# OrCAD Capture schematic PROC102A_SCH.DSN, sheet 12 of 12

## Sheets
12 09.IO LINK TRANCIEVER[4:8]: size C; title: IO LINK TRANCIEVER[5:8]
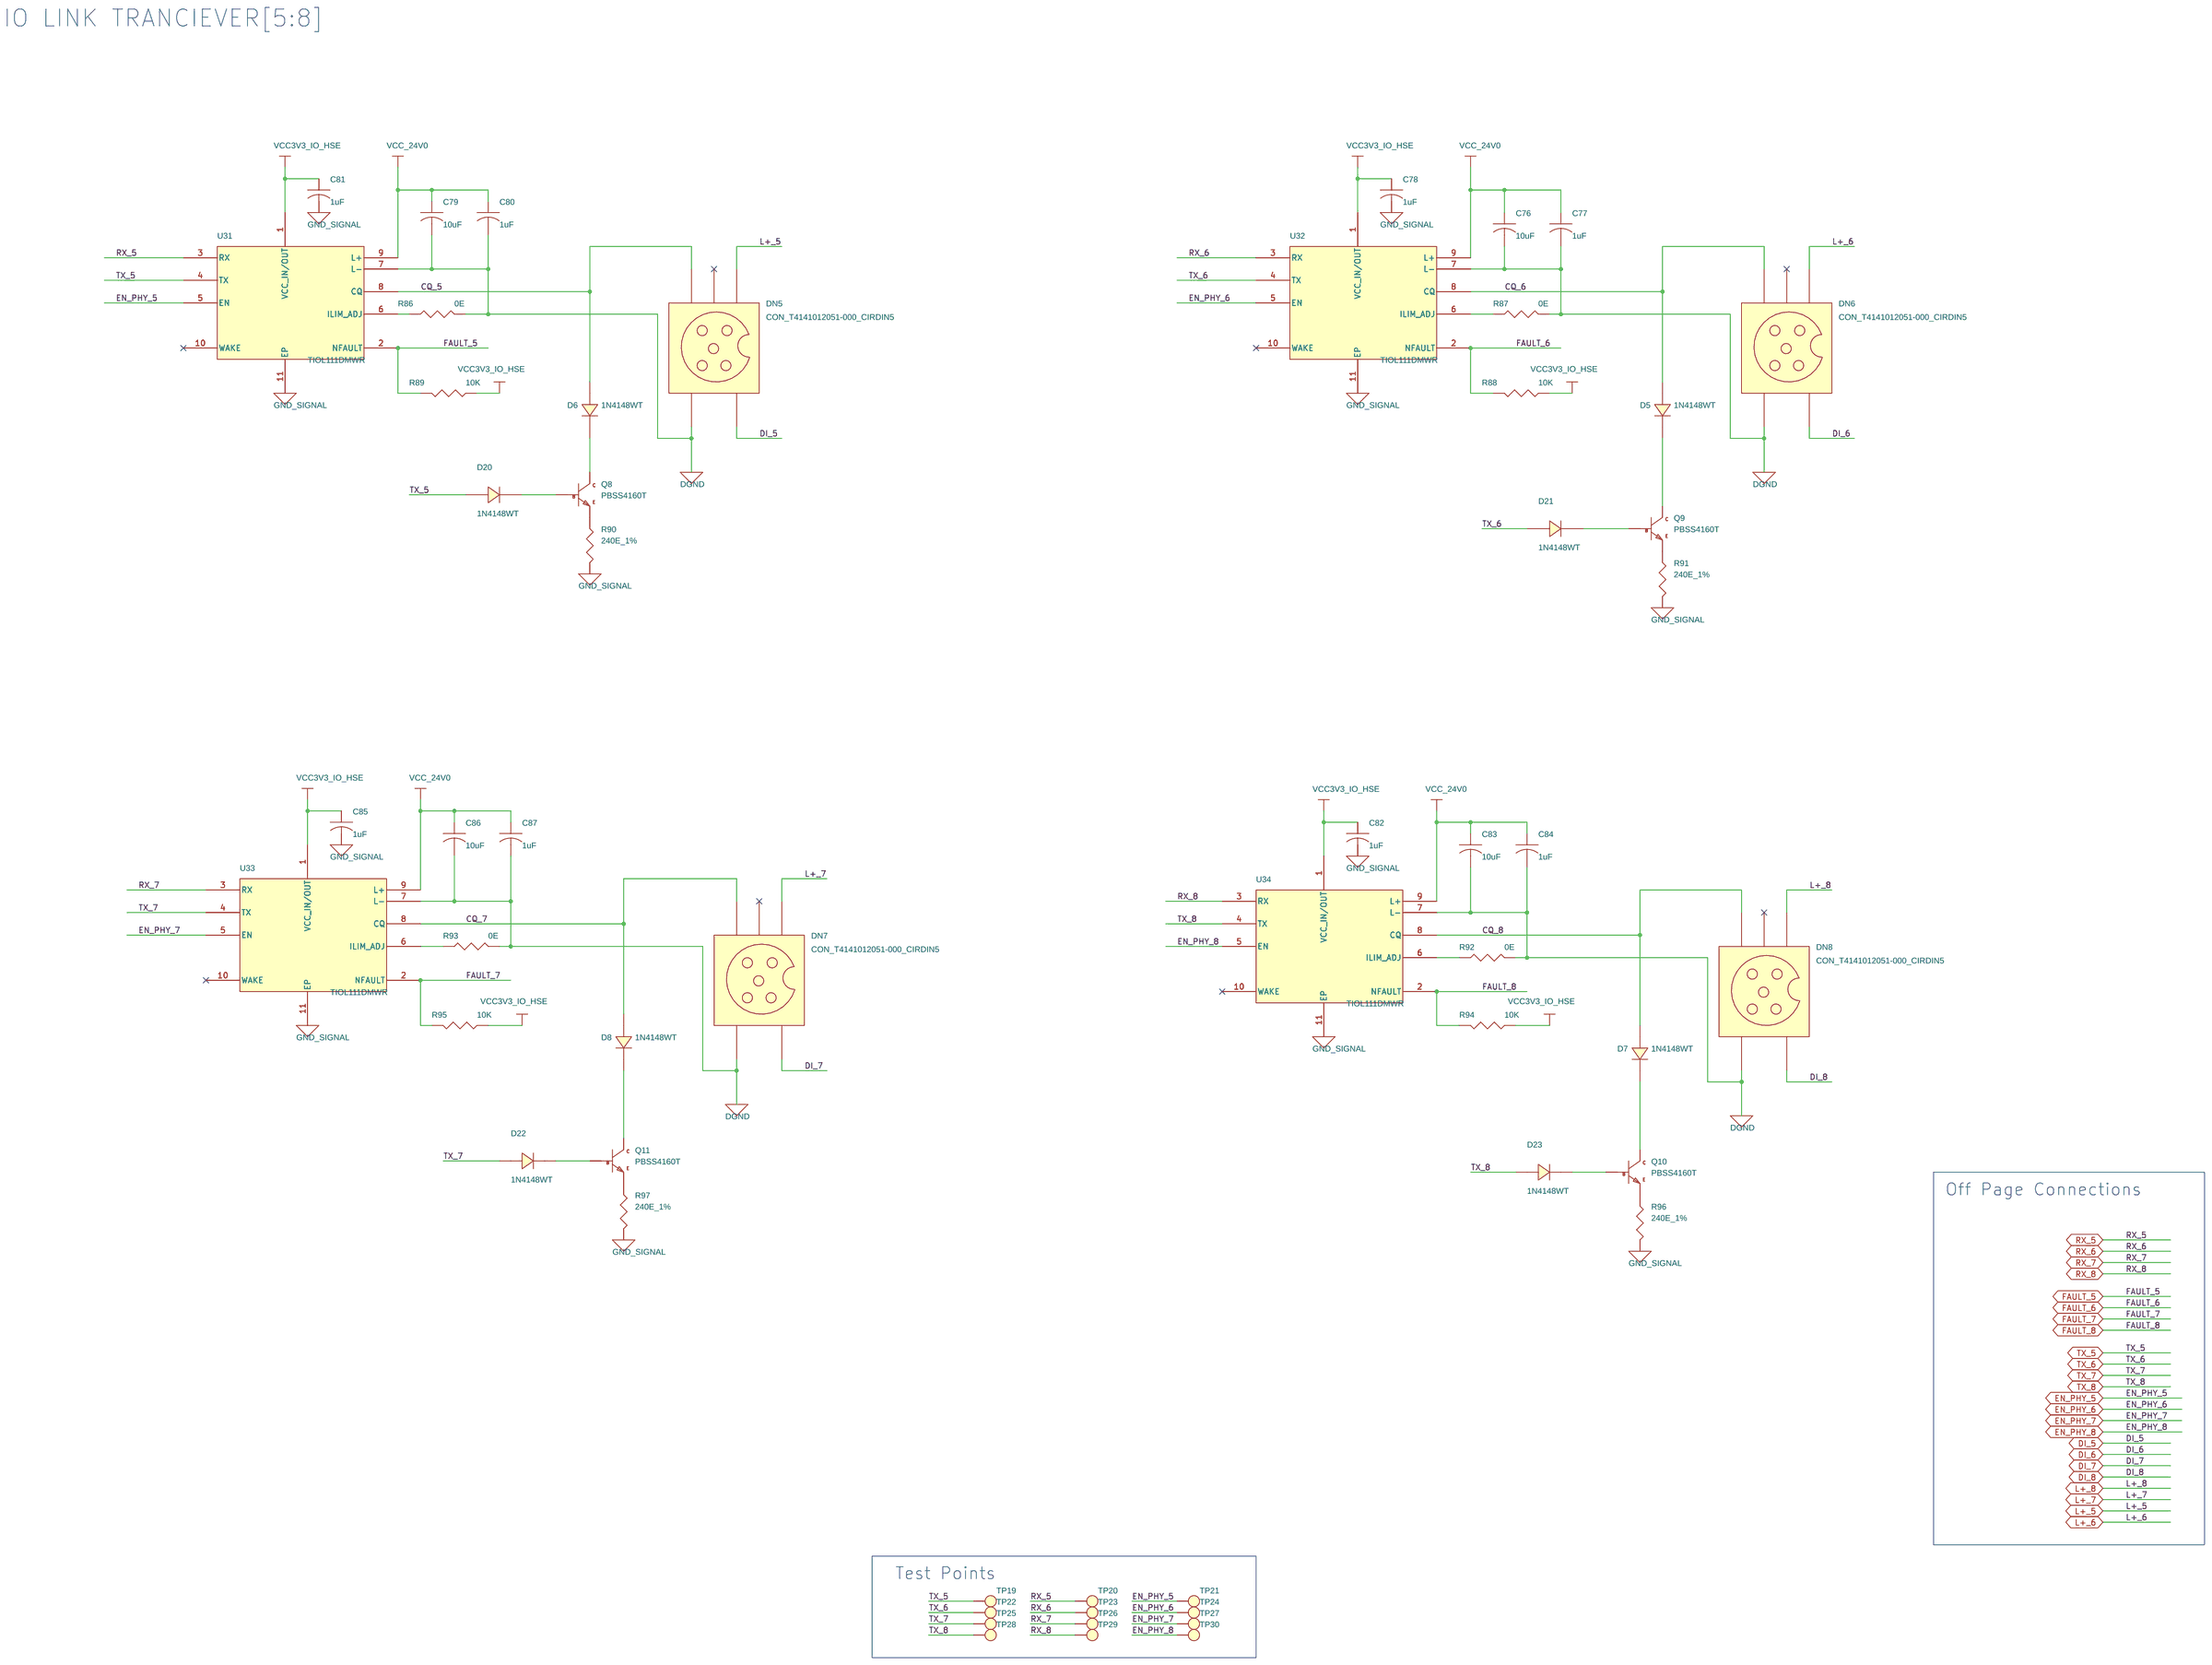
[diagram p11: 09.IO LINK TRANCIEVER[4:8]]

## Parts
C76  10uF  [CAP1206_2]
C77  1uF  [CAP0805_1-5]
C78  1uF  [CAP0402_0-75]
C79  10uF  [CAP1206_2]
C80  1uF  [CAP0805_1-5]
C81  1uF  [CAP0402_0-75]
C82  1uF  [CAP0402_0-75]
C83  10uF  [CAP1206_2]
C84  1uF  [CAP0805_1-5]
C85  1uF  [CAP0402_0-75]
C86  10uF  [CAP1206_2]
C87  1uF  [CAP0805_1-5]
D5  1N4148WT  [DIO_SOD523]
D6  1N4148WT  [DIO_SOD523]
D7  1N4148WT  [DIO_SOD523]
D8  1N4148WT  [DIO_SOD523]
D20  1N4148WT  [DIO_SOD523]
D21  1N4148WT  [DIO_SOD523]
D22  1N4148WT  [DIO_SOD523]
D23  1N4148WT  [DIO_SOD523]
DN5  CON_T4141012051-000_CIRDIN5  [CON_CIRDIN5_T4141012051_S_S_T_23]
DN6  CON_T4141012051-000_CIRDIN5  [CON_CIRDIN5_T4141012051_S_S_T_23]
DN7  CON_T4141012051-000_CIRDIN5  [CON_CIRDIN5_T4141012051_S_S_T_23]
DN8  CON_T4141012051-000_CIRDIN5  [CON_CIRDIN5_T4141012051_S_S_T_23]
Q8  PBSS4160T  [SOT23-123_1-1]
Q9  PBSS4160T  [SOT23-123_1-1]
Q10  PBSS4160T  [SOT23-123_1-1]
Q11  PBSS4160T  [SOT23-123_1-1]
R86  0E  [RES0402_0-5]
R87  0E  [RES0402_0-5]
R88  10K  [RES0402_0-5]
R89  10K  [RES0402_0-5]
R90  240E_1%  [RES0402_0-5]
R91  240E_1%  [RES0402_0-5]
R92  0E  [RES0402_0-5]
R93  0E  [RES0402_0-5]
R94  10K  [RES0402_0-5]
R95  10K  [RES0402_0-5]
R96  240E_1%  [RES0402_0-5]
R97  240E_1%  [RES0402_0-5]
TP19  TP20_SMD  [TP20_SMD]
TP20  TP20_SMD  [TP20_SMD]
TP21  TP20_SMD  [TP20_SMD]
TP22  TP20_SMD  [TP20_SMD]
TP23  TP20_SMD  [TP20_SMD]
TP24  TP20_SMD  [TP20_SMD]
TP25  TP20_SMD  [TP20_SMD]
TP26  TP20_SMD  [TP20_SMD]
TP27  TP20_SMD  [TP20_SMD]
TP28  TP20_SMD  [TP20_SMD]
TP29  TP20_SMD  [TP20_SMD]
TP30  TP20_SMD  [TP20_SMD]
U31  TIOL111DMWR  [VSON10_19-68_120X100_1]
U32  TIOL111DMWR  [VSON10_19-68_120X100_1]
U33  TIOL111DMWR  [VSON10_19-68_120X100_1]
U34  TIOL111DMWR  [VSON10_19-68_120X100_1]

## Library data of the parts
C76 C79 C83 C86 = CAP: CAP CERAMIC 10uF 50V 10% X5R AUTO 1206; Chkd/date: MANIRAJA/261018; Crtd /date: ALVY/261018; Custom_Duty: 15%; Customs_HS_Code: 85322990; Distributor_name: DIGIKEY; Distributor_part_number: 490-12456-1-ND; Footprint Path: Y:\MIS_DATABASE\Library\ALTIUM_TOOL\PCB_FOOTPRINTS\Altium_Footprint_Lib.PcbLib; Height: 1.80MM; Library Path: Y:\MIS_DATABASE\Library\ALTIUM_TOOL\SCHEMATICS_PARTS\MS_DISCRETE_Library.schlib; Mfr_name: MURATA; Mfr_part_number: GRT31CR61H106KE01L; Mistral Part No: 120011060019-R; Package: 1206; Part_type: CAPACITORS\CERAMIC; Project: LRDE_ABCMV2_MB; RoHS: RoHS; Temperature: -55°C+85°C; Tolerance: 10%; Voltage: 50V; Wattage: NA; Weight: 16.2mg; Datasheet: Y:\MIS_DATABASE\DATASHEETS\CAPACITORS\GRT31CR61H106KE01L.PDF
C77 C80 C84 C87 = CAP: CAP CERAMIC 1uF 50V 10% X7R 0805; Chkd/date: MANIRAJA/100920; Crtd /date: ALVY/100920; Custom_Duty: 15%; Customs_HS_Code: 85322990; Distributor_name: DIGIKEY; Distributor_part_number: 732-7678-1-ND; Footprint Path: Y:\MIS_DATABASE\Library\ALTIUM_TOOL\PCB_FOOTPRINTS\Altium_Footprint_Lib.PcbLib; Height: 1.35MM; Library Path: Y:\MIS_DATABASE\Library\ALTIUM_TOOL\SCHEMATICS_PARTS\MS_DISCRETE_Library.schlib; Mfr_name: WURTH ELECTRONICS; Mfr_part_number: 885012207103; Mistral Part No: 120011010018-R; Package: 0805; Part_type: CAPACITORS\CERAMIC; Project: AM64x-IO LINK BRD; RoHS: RoHS; Temperature: -55°C+125°C; Tolerance: 10%; Voltage: 50V; Wattage: NA; Weight: 36mg; Datasheet: Y:\MIS_DATABASE\DATASHEETS\CAPACITORS\885012207103.PDF
C78 C81 C82 C85 = CAP: CAP CERAMIC 1uF 10V 20% X5R 0402; Chkd/date: MANIRAJA/210820; Crtd /date: ALVY/190820; Custom_Duty: 15%; Customs_HS_Code: 85322990; Distributor_name: DIGIKEY; Distributor_part_number: 732-7489-1-ND; Footprint Path: Y:\MIS_DATABASE\Library\ALTIUM_TOOL\PCB_FOOTPRINTS\Altium_Footprint_Lib.PcbLib; Height: 0.55MM; Library Path: Y:\MIS_DATABASE\Library\ALTIUM_TOOL\SCHEMATICS_PARTS\MS_DISCRETE_Library.schlib; Mfr_name: WURTH ELECTRONICS; Mfr_part_number: 885012105012; Mistral Part No: 120020080009-R; Package: 0402; Part_type: CAPACITORS\CERAMIC; Project: AM64x_EVM_BRD; RoHS: RoHS; Temperature: -55°C+85°C; Tolerance: 20%; Voltage: 10V; Wattage: NA; Weight: 0.65mg; Datasheet: Y:\MIS_DATABASE\DATASHEETS\CAPACITORS\885012105012.PDF
D5-D8 D20-D23 = DIODE: DIODE SWITCH 75V 10mA SOD523; Chkd/date: SUHAS/041010; Crtd /date: MAZHAR/110210; Custom_Duty: 15%; Customs_HS_Code: 85412900; Distributor_name: DIGIKEY; Distributor_part_number: 1N4148WTCT-ND; Height: 0.70MM; Mfr_name: FAIRCHILD; Mistral Part No: 130010020017-R; Package: SOD523; Part_type: DIODE\SWITCHING; Project: NPOL_PREAMP; RoHS: RoHS; Temperature: -55°C+150°C; Tolerance: 20%; Voltage: 75V; Weight: NA; Datasheet: Y:\MIS_DATABASE\DATASHEETS\DISCRETES\DIODES\1N4148WT-F.PDF
DN5-DN8 = CON_T4143012051_CIRDIN5_S: CON CIRCULAR 5POS FEMALE ST TH; Chkd/date: MANIRAJA/280820; Crtd /date: ALVY/280820; Custom_Duty: 24%; Customs_HS_Code: 85369090; Distributor_name: DIGIKEY; Distributor_part_number: A126851-ND; Footprint Path: Y:\MIS_DATABASE\Library\ALTIUM_TOOL\PCB_FOOTPRINTS\Altium_Footprint_Lib.PcbLib; Height: 23.00MM; Library Path: Y:\MIS_DATABASE\Library\ALTIUM_TOOL\SCHEMATICS_PARTS\MS_CONNECTOR_Library.schlib; Mfr_name: TE CONNECTIVITY; Mfr_part_number: T4141012051-000; Mistral Part No: 150020080008-R; Package: THRU-HOLE; Part_type: CONNECTOR\CIRDIN; Project: AM64x_EVM_TESTJIG_BRD; RoHS: RoHS; Temperature: -40°C+85°C; Tolerance: NA; Voltage: NA; Wattage: NA; Weight: 16500mg; Datasheet: Y:\MIS_DATABASE\DATASHEETS\CONNECTORS\T41410120X1-000.PDF
Q8-Q11 = NPN_123_SOT23-3: TRANSISTOR NPN 60V 1A SOT23-3; Chkd/date: MANIRAJA/220720; Crtd /date: ALVY/210720; Custom_Duty: 15%; Customs_HS_Code: 85412900; Distributor_name: DIGIKEY; Distributor_part_number: 1727-3939-1-ND; Footprint Path: Y:\MIS_DATABASE\Library\ALTIUM_TOOL\PCB_FOOTPRINTS\Altium_Footprint_Lib.PcbLib; Height: 1.10MM; Library Path: Y:\MIS_DATABASE\Library\ALTIUM_TOOL\SCHEMATICS_PARTS\MS_TRANSISTOR_Library.schlib; Mfr_name: NXP SEMICONDUCTORS; Mfr_part_number: PBSS4160T,215; Mistral Part No: 130020070017-R; Package: SOT23-3; Part_type: TRANSISTOR\BIPOLAR; Project: AM64x-IO LINK BRD; RoHS: RoHS; Temperature: -65°C+150°C; Tolerance: NA; Voltage: NA; Wattage: NA; Weight: 8mg; Datasheet: Y:\MIS_DATABASE\DATASHEETS\DISCRETES\TRANSISTORS_FETS\PBSS4160T.PDF
R86 R87 R92 R93 = RESISTOR: RES 0E 1/16W JUMPER 0402; Chkd/date: VASANTHA/201216; Crtd /date: MUDDU/190810; Custom_Duty: 15%; Customs_HS_Code: 85332119; Distributor_name: DIGIKEY; Distributor_part_number: 541-0.0JCT-ND; Footprint Path: Y:\MIS_DATABASE\Library\ALTIUM_TOOL\PCB_FOOTPRINTS\Altium_Footprint_Lib.PcbLib; Height: 0.40MM; Library Path: Y:\MIS_DATABASE\Library\ALTIUM_TOOL\SCHEMATICS_PARTS\MS_DISCRETE_Library.schlib; Mfr_name: VISHAY; Mfr_part_number: CRCW04020000Z0ED; Mistral Part No: 110010080019-R; Package: 0402; Part_type: RESISTORS\FIXED; Project: PB_BUGBASE; RoHS: RoHS; Temperature: -55°C+155°C; Tolerance: NA; Voltage: NA; Wattage: 1/16W; Weight: 0.65mg; Datasheet: Y:\MIS_DATABASE\DATASHEETS\RESISTORS\CRCW0603.PDF
R88 R89 R94 R95 = RESISTOR: RES 10K 1/16W 5% 0402; Chkd/date: VASANTHA/061216; Crtd /date: MAZHAR/230805; Custom_Duty: 15%; Customs_HS_Code: 85332119; Distributor_name: DIGIKEY; Distributor_part_number: 311-10KJRCT-ND; Footprint Path: Y:\MIS_DATABASE\Library\ALTIUM_TOOL\PCB_FOOTPRINTS\Altium_Footprint_Lib.PcbLib; Height: 0.40MM; Library Path: Y:\MIS_DATABASE\Library\ALTIUM_TOOL\SCHEMATICS_PARTS\MS_DISCRETE_Library.schlib; Mfr_name: YAGEO AMERICA; Mfr_part_number: RC0402JR-0710KL; Mistral Part No: 110011060021-R; Package: 0402; Part_type: RESISTORS\FIXED; Project: HSE; RoHS: RoHS; Temperature: -55°C+155°C; Tolerance: 5%; Voltage: NA; Wattage: 1/16W; Weight: 0.65mg; Datasheet: Y:\MIS_DATABASE\DATASHEETS\RESISTORS\RCXXXXL-SER_MAR18.PDF
R90 R91 R96 R97 = RESISTOR: RES 240E 1/10W 1% 0402; Chkd/date: MAZHAR/150611; Crtd /date: BAVISH/020611; Custom_Duty: 15%; Customs_HS_Code: 85332119; Distributor_name: DIGIKEY; Distributor_part_number: P240LCT-ND; Footprint Path: Y:\MIS_DATABASE\Library\ALTIUM_TOOL\PCB_FOOTPRINTS\Altium_Footprint_Lib.PcbLib; Height: 0.40MM; Library Path: Y:\MIS_DATABASE\Library\ALTIUM_TOOL\SCHEMATICS_PARTS\MS_DISCRETE_Library.schlib; Mfr_name: PANASONIC-ECG; Mfr_part_number: ERJ-2RKF2400X; Mistral Part No: 110011060017-R; Package: 0402; Part_type: RESISTORS\FIXED; Project: AM4515_EVM_LCD; RoHS: RoHS; Temperature: -55°C+155°C; Tolerance: 1%; Voltage: NA; Wattage: 1/10W; Weight: 0.8mg; Datasheet: Y:\MIS_DATABASE\DATASHEETS\RESISTORS\PAN-ERJSER_NOV17.PDF
TP19-TP30 = TESTPOINT: TESTPOINT CIR 20 SMD; Chkd/date: SHREESHAIL/171006; Crtd /date: MAZHAR/171006; Custom_Duty: NA; Customs_HS_Code: NA; Distributor_name: NA; Distributor_part_number: NA; Footprint Path: Y:\MIS_DATABASE\Library\ALTIUM_TOOL\PCB_FOOTPRINTS\Altium_Footprint_Lib.PcbLib; Height: NA; Library Path: Y:\MIS_DATABASE\Library\ALTIUM_TOOL\SCHEMATICS_PARTS\MS_DISCRETE_Library.schlib; MECHANICAL 3D STEP FILE: NA; Mfr_name: LOCAL; Mistral Part No: NA; Package: SMD; Project: BT MODULE_CSRBC04; RoHS: NA; Temperature: NA; Tolerance: NA; Voltage: NA; Wattage: NA; Weight: NA; Datasheet: NA
U31-U34 = TIOL111_VSON10: IC IO-LINK DEVICE TRANSCEIVER WITH INTEGRATED SURGE PROTECTION VSON10; Chkd/date: MANIRAJA/210720; Crtd /date: ALVY/170720; Custom_Duty: 15%; Customs_HS_Code: 85423100; Distributor_name: DIGIKEY; Distributor_part_number: 296-49943-1-ND; Footprint Path: Y:\MIS_DATABASE\Library\ALTIUM_TOOL\PCB_FOOTPRINTS\Altium_Footprint_Lib.PcbLib; Height: 1.00MM; Library Path: Y:\MIS_DATABASE\Library\ALTIUM_TOOL\SCHEMATICS_PARTS\MS_MISCINTERFACE_Library.schlib; Mfr_name: TEXAS INSTRUMENTS; Mistral Part No: 141020070002-R; Package: VSON10; Part_type: ICS\INTERFACE\TRANSCEIVER; Project: AM64x-GP_EVM BRD; RoHS: RoHS; Temperature: -40°C+125°C; Tolerance: NA; Voltage: NA; Wattage: NA; Weight: 19mg; Datasheet: Y:\MIS_DATABASE\DATASHEETS\ICS\DIGITAL\BUSTRANSCEIVER\TIOL111.PDF

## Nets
DGND: C76.2 C77.2 C78.2 C79.2 C80.2 C81.2 C82.2 C83.2 C84.2 C85.2 C86.2 C87.2 DN5.3 DN6.3 DN7.3 DN8.3 R86.2 R87.2 R90.2 R91.2 R92.2 R93.2 R96.2 R97.2 U31.7(L-) U31.11(EP) U32.7(L-) U32.11(EP) U33.7(L-) U33.11(EP) U34.7(L-) U34.11(EP) ; also on sheet 5 6 7 8 9 10 11
VCC3V3_IO_HSE: C78.1 C81.1 C82.1 C85.1 R88.2 R89.2 R94.2 R95.2 U31.1(VCC_IN/OUT) U32.1(VCC_IN/OUT) U33.1(VCC_IN/OUT) U34.1(VCC_IN/OUT) ; also on sheet 5 6 7 8 9 10 11
VCC_24V0: C76.1 C77.1 C79.1 C80.1 C83.1 C84.1 C86.1 C87.1 U31.9(L+) U32.9(L+) U33.9(L+) U34.9(L+) ; also on sheet 8 9 10 11
CQ_5: D6.2(A) DN5.4 U31.8(CQ)
CQ_6: D5.2(A) DN6.4 U32.8(CQ)
CQ_7: D8.2(A) DN7.4 U33.8(CQ)
CQ_8: D7.2(A) DN8.4 U34.8(CQ)
DI_5: DN5.2 ; also on sheet 9
DI_6: DN6.2 ; also on sheet 9
DI_7: DN7.2 ; also on sheet 9
DI_8: DN8.2 ; also on sheet 9
EN_PHY_5: TP21.1(TP) U31.5(EN) ; also on sheet 6
EN_PHY_6: TP24.1(TP) U32.5(EN) ; also on sheet 6
EN_PHY_7: TP27.1(TP) U33.5(EN) ; also on sheet 6
EN_PHY_8: TP30.1(TP) U34.5(EN) ; also on sheet 6
FAULT_5: R89.1 U31.2(NFAULT) ; also on sheet 7
FAULT_6: R88.1 U32.2(NFAULT) ; also on sheet 7
FAULT_7: R95.1 U33.2(NFAULT) ; also on sheet 7
FAULT_8: R94.1 U34.2(NFAULT) ; also on sheet 7
L+_5: DN5.1 ; also on sheet 9
L+_6: DN6.1 ; also on sheet 9
L+_7: DN7.1 ; also on sheet 9
L+_8: DN8.1 ; also on sheet 9
RX_5: TP20.1(TP) U31.3(RX) ; also on sheet 6
RX_6: TP23.1(TP) U32.3(RX) ; also on sheet 6
RX_7: TP26.1(TP) U33.3(RX) ; also on sheet 6
RX_8: TP29.1(TP) U34.3(RX) ; also on sheet 6
TX_5: D20.2(A) TP19.1(TP) U31.4(TX) ; also on sheet 6
TX_6: D21.2(A) TP22.1(TP) U32.4(TX) ; also on sheet 6
TX_7: D22.2(A) TP25.1(TP) U33.4(TX) ; also on sheet 6
TX_8: D23.2(A) TP28.1(TP) U34.4(TX) ; also on sheet 6
N17194207: R87.1 U32.6(ILIM_ADJ)
N17194223: D5.1(K) Q9.3(COLLECTOR)
N17194517: R86.1 U31.6(ILIM_ADJ)
N17194572: D6.1(K) Q8.3(COLLECTOR)
N17194628: R92.1 U34.6(ILIM_ADJ)
N17194647: D7.1(K) Q10.3(COLLECTOR)
N17196536: R93.1 U33.6(ILIM_ADJ)
N17196560: D8.1(K) Q11.3(COLLECTOR)
N17220978: Q11.2(EMITTER) R97.1
N17220979: Q10.2(EMITTER) R96.1
N17220982: Q8.2(EMITTER) R90.1
N17220983: Q9.2(EMITTER) R91.1
N17284279: D20.1(K) Q8.1(BASE)
N17284317: D21.1(K) Q9.1(BASE)
N17284361: D22.1(K) Q11.1(BASE)
N17284397: D23.1(K) Q10.1(BASE)

Not connected (* = marked no-connect by the designer): DN5 5*; DN6 5*; DN7 5*; DN8 5*; U31 10(WAKE)*; U32 10(WAKE)*; U33 10(WAKE)*; U34 10(WAKE)*

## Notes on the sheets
sheet 12
- IO LINK TRANCIEVER[5:8]
- Off Page Connections
- Test Points
